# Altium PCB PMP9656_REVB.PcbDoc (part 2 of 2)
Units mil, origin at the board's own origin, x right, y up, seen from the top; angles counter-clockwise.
Board outline 5000 x 2000 mil, 4 copper layers (Top Layer, MidLayer1, MidLayer2, Bottom Layer), stack 60.2 mil thick; 89 components, 41 nets, 276 pads, 85 vias.
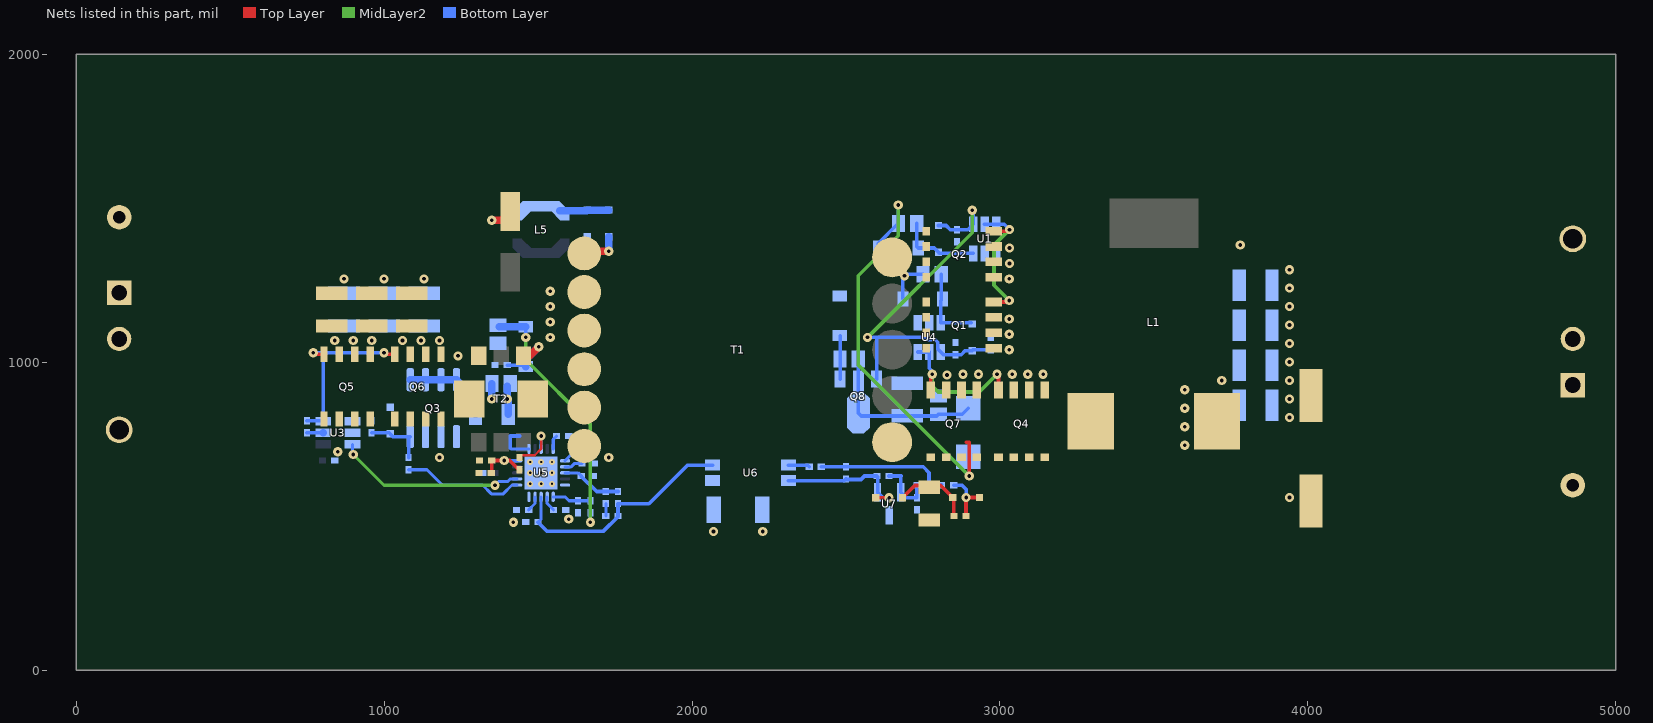
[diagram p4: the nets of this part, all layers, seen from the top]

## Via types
v1: diameter 30, hole 12, Top Layer to Bottom Layer, 76 vias
v2: diameter 19.68, hole 7.87, Top Layer to Bottom Layer, 9 vias

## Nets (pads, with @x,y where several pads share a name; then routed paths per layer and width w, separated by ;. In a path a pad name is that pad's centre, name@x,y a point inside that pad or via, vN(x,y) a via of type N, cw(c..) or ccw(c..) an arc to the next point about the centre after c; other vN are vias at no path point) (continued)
CS: D4.1 R5.2 R10.1 | length 836.7
  MidLayer2 w12: v1(1460,1080) 1460,1007.5 1670,797.5 v1(1670,480)
  Bottom Layer w12: v1(1460,1080) D4.1@1460,1114.47 ; v1(1670,480) R10.1@1670,510.32
  Bottom Layer w25: R5.2@1375.06,1114.47 D4.1@1460,1114.47
GND: C1.2 C2.1 C9.2 C10.2 C11.2 C12.2 C13.2 C16.2 C18.2 C20.2 C33.2 D12.2 J2.2 Q1.1 Q1.2 Q1.3 Q2.1 Q2.2 Q2.3 Q4.1 Q4.2 Q4.3 Q7.1 Q7.2 Q7.3 R2.1 R29.1 TP4.1 U1.4 U1.5 U4.4 U4.5 U7.3
  other v1: 2230,450 3940,560 3720,940 2827.65,958 2880,960 2930,960 3040,960 3090,960 3140,960 3030,1040 3030,1090 3030,1140 3030,1270 3030.71,1320 3030.71,1370 3780,1380
N_DRV: U3.6 U5.12 | length 611.9
  MidLayer2 w10: v1(900,700) 1000,600 v1(1360,600)
  Bottom Layer w10: v1@897.24,702.76 U3.6@897.24,732.6 ; v1(1360,600) 1372,612 1401.6,612 1409.91,620.32 U5.12@1432.24,620.32
NetC14_1: C14.1 Q3.5 Q3.6 Q3.7 Q3.8 | length 288.1
  Bottom Layer w25: Q3.5@1085,942.52 Q3.6@1135,942.52 Q3.7@1185,942.52 Q3.8@1235,942.52 1296.85,880.67 C14.1@1296.85,830
NetC14_2: C14.2 R3.2 T1.4 T1.5 T2.8 | length 91.8
  Bottom Layer w25: R3.2@1400,920.47 v1(1400,880) 1403.15,876.85 C14.2@1403.15,830
NetC15_2: C15.2 D5.2 Q3.4 R4.2 | length 195.1
  Bottom Layer w12: R4.2@960,770.31 D5.2@1016.38,770.31 ; D5.2@1020,766.69 1029.21,757.48 Q3.4@1085,757.48 1080,752.48 C15.2@1080,689.69
NetC16_1: C16.1 D3.1 Q8.2 Q8.4 R2.2 R7.2 | length 546.4
  Bottom Layer w12: R7.2@2540,1009.53 Q8.2@2540,936.93 Q8.4@2540,834.57 2549.54,825.03 R2.2@2698.13,825.03 2794.56,825.03 C16.1@2800,830.47 2877.3,830.47 D3.1@2897.09,850.26
NetC22_2: C22.2 R10.2 U5.6 | length 125.8
  Bottom Layer w10: U5.6@1549.37,562.24 1587.76,562.24 1600.31,549.69 C22.2@1630,549.69 R10.2@1670,549.69
NetC23_2: C23.2 U5.9 | length 50.8
  Bottom Layer w10: C23.2@1469.69,520 1490.32,540.63 U5.9@1490.32,562.24
NetC25_2: C25.2 R12.1 R17.2 U5.15 | length 185
  Top Layer w12: C25.2@1347.87,640 1349.69,641.81 R17.2@1349.69,680 v1(1390,680) 1408.23,680 1437.92,650.32 R12.1@1440,650.32
  Bottom Layer w10: v1@1390.63,679.37 U5.15@1432.24,679.37
NetC27_1: C27.1 D10.2 R23.1 U6.2 U7.1 | length 432.4
  Top Layer w12: D10.2@2596.69,559.68 v1(2640,559.68)
  Bottom Layer w12: U6.2@2313.03,615 2494.68,615 R23.1@2500,620.32 ; R23.1@2500,618.86 2548.86,618.86 2560,630 C27.1@2600.32,630 ; C27.1@2602.6,627.72 U7.1@2602.6,577.4 2620.32,559.68 v1(2640,559.68)
NetC27_2: C27.2 R24.1 R29.2 U7.2 | length 193.9
  Bottom Layer w12: C27.2@2639.69,630 2679.68,630 2677.4,627.72 U7.2@2677.4,577.4 2695.12,559.69 R29.2@2730,559.69 2730,599.68 R24.1@2730.32,600
NetC29_1: C29.1 R25.1 R26.1 U5.3 | length 198.4
  Bottom Layer w10: U5.3@1587.76,640 1630.32,640 C29.1@1640.32,630
  Bottom Layer w12: C29.1@1640.32,630 1640.32,627.92 1662.08,606.16 1664.16,606.16 1690.63,579.68 R25.1@1720,579.68 R26.1@1760,579.68
NetC31_1: C31.1 C32.1 R26.2 U5.8 U6.4 | length 779.1
  Bottom Layer w10: C32.1@1499.68,480 1510,490.32 U5.8@1510,562.24
  Bottom Layer w12: C32.1@1499.68,480 1528.68,451 1712.77,451 1759.68,497.92 C31.1@1759.68,500 1759.68,540 1860,540 1985,665 U6.4@2066.97,665
NetC31_2: C31.2 R25.2 | length 40
  Bottom Layer w10: C31.2@1720.31,500 R25.2@1720.31,540
NetC33_1: C33.1 D10.1 D11.2 R28.1 | length 257.6
  Top Layer w12: D10.1@2683.31,559.68 2722.99,599.37 2770,599.37 2807.32,599.37 D11.2@2846.69,560 2850.32,556.38 R28.1@2850.32,500
NetD1_2: D1.2 D2.2 R1.2 U1.6 | length 267.3
  Bottom Layer w12: R1.2@2729.53,1450 2729.53,1374.94 D2.2@2734.47,1370 2786.69,1370 D1.2@2800,1356.69 2803.94,1352.76 U1.6@2912.6,1352.76
NetD4_2: D4.2 R6.2 T2.1 | length 206.2
  Top Layer w25: T2.1@1453,1020 1472.5,1020 v1(1502.5,1050)
  Bottom Layer w12: R6.2@1399.69,990 1455.53,990 D4.2@1460,985.53
  Bottom Layer w25: D4.2@1460,985.53 1460,1007.5 v1(1502.5,1050)
NetD6_1: D6.1 D7.1 L5.2 | length 159.9
  Bottom Layer w25: L5.2@1571.02,1491.02 1657.72,1491.02 D7.1@1660,1493.31 D6.1@1730,1493.31
NetD6_2: D6.2 T1.1 | length 129.8
  Top Layer w25: T1.1@1650,1352.6 1657.4,1360 v1(1730,1360)
  Bottom Layer w25: v1(1730,1360) D6.2@1730,1406.69
NetD8_2: D8.2 D9.2 R9.2 U4.6 | length 257
  Bottom Layer w12: R9.2@2808.85,1285 2808.85,1200.22 2807.4,1198.77 U4.6@2807.4,1127.24 D8.2@2906.06,1127.24
NetD12_1: D12.1 Q8.1 R7.1 | length 139.8
  Bottom Layer w12: Q8.1@2480.94,944.8 D12.1@2480.94,1084.59
NetQ1_4: Q1.4 Q2.4 U1.2 U1.3 | length 451.1
  Top Layer w12: Q1.4@2979.3,1195 v1@3025,1195 ; Q2.4@2979.3,1425 v1@3025.71,1425
  MidLayer2 w12: v1(3030,1200) 2980.69,1249.31 2980.69,1379.98 v1(3030.71,1430)
  Bottom Layer w12: U1.2@2950,1447.24 U1.3@2987.4,1447.24 3013.46,1447.24 v1(3030.71,1430)
NetQ4_4: Q4.4 Q7.4 U4.2 U4.3 | length 485.5
  Top Layer w12: Q7.4@2775,909.3 v1@2775,955 ; Q4.4@2995,909.3 v1@2995,955
  MidLayer2 w12: v1(2780,960) 2780,922.14 2799.61,902.52 2932.52,902.52 v1(2990,960)
  Bottom Layer w12: U4.3@2732.6,1032.76 U4.2@2770,1032.76 2770,980 2780,970 v1(2780,960)
NetQ5_4: Q5.4 Q6.4 R100.2 U3.3 | length 567.7
  Top Layer w12: v1@774.88,1025.12 Q5.4@805,1025.12 ; v1@1004.88,1025.12 Q6.4@1035,1025.12
  Bottom Layer w12: R100.2@750,809.69 800.47,809.69 U3.3@802.76,807.4 802.76,1027.24 800,1030 ; v1(770,1030) 800,1030 ; v1(1000,1030) 800,1030
NetQ5_5: Q5.5 Q5.6 Q5.7 Q5.8 Q6.5 Q6.6 Q6.7 Q6.8 R3.1 T2.7 | length 49.5
  Bottom Layer w25: v1(1350,880) R3.1@1350,929.53
NetR13_2: R13.2 R20.2 R23.2 R24.2 | length 439.7
  Bottom Layer w12: R20.2@2419.69,660 R23.2@2499.69,660 ; R23.2@2500,659.69 2750.63,659.69 2769.69,640.63 R24.2@2769.69,600 R13.2@2810.31,600 R13.2@2810.31,600.82
NetR14_2: R14.2 U5.20 | length 46.8
  Bottom Layer w10: U5.20@1549.37,717.76 1549.37,749.06 R14.2@1560.31,760
NetR15_2: R15.2 U5.7 | length 50.8
  Bottom Layer w10: U5.7@1529.68,562.24 1529.68,540.63 R15.2@1550.31,520
NetR19_2: R19.2 U5.1 | length 65.2
  Bottom Layer w10: U5.1@1587.76,679.37 1618.39,710 R19.2@1640.31,710
NetR20_1: R20.1 U6.1 | length 69.4
  Bottom Layer w12: U6.1@2313.03,665 2375.32,665 R20.1@2380.32,660
NetR22_2: R22.2 U5.2 | length 60.1
  Bottom Layer w10: U5.2@1587.76,659.68 1607.63,659.68 1619,671.05 R22.2@1643.16,671.05
NetR100_1: R100.1 U3.2 | length 52.9
  Bottom Layer w12: R100.1@750,770.32 U3.2@802.44,770.32
  Bottom Layer w25: U3.2@802.44,770.32 U3.2@802.76,770
P_DRV: C15.1 U5.11 | length 396.5
  Bottom Layer w10: C15.1@1080,650.32 1139.68,650.32 1189.37,600.63 1319.77,600.63 1348.4,572 1387.05,572 1415.68,600.63 U5.11@1432.24,600.63
PGND: C2.2 C3.2 C4.2 C5.2 C6.2 C7.2 C8.2 C19.1 C21.2 C22.1 C23.1 C25.1 C28.2 C29.2 C32.2 D5.1 D7.2 J1.2 Q3.1 Q3.2 Q3.3 Q5.1 Q5.2 Q5.3 Q6.1 Q6.2 Q6.3 R4.1 R5.1 R6.1 R14.1 R15.1 R17.1 R19.1 R22.1 T1.6 T2.3 TP3.1 U3.4 U3.5 U5.5 U5.10 U5.16 U5.21 U6.3 | length 201.1
  Top Layer w25: v1(1350,1460) 1381.57,1460 C21.2@1410,1488.43
  Bottom Layer w10: 1411.93,717.76 U5.16@1470.63,717.76
  Bottom Layer w12: 1409.69,720 1409.69,760 1440.32,760
  other v1: 2070,450 1420,480 1600,490 1180,690 1730,690 850,708.98 1240,1020 840,1070 900,1070 960,1070 1060,1070 1120,1070 1180,1070
  other v2: 1474.57,604.57 1510,604.57 1545.43,604.57 1474.57,640 1510,640 1545.43,640 1474.57,675.43 1510,675.43 1545.43,675.43
VDRV: C1.1 C18.1 C20.1 D1.1 D8.1 Q8.3 U1.1 U4.1 | length 1300.2
  MidLayer2 w12: v1(2570,1080) 2910,1420 v1(2910,1492.52)
  Bottom Layer w12: v1(2570,1080) 2600,1080 ; Q8.3@2599.06,944.8 2600.32,946.06 2600.32,1079.68 2600,1080 ; D1.1@2800,1443.31 2824.67,1443.31 2838.3,1429.68 C1.1@2860,1429.68 2895.04,1429.68 U1.1@2912.6,1447.24 v1@2912.6,1489.92 ; C18.1@2970,1040.32 2913.62,1040.32 D8.1@2910,1036.69 2886.69,1036.69 2873.86,1023.86 C20.1@2855.3,1023.86 2816.3,1023.86 U4.1@2807.4,1032.76 2797.78,1042.38 2797.78,1064.15 2789.58,1072.35 2767.81,1072.35 2760.16,1080 2600,1080
VIN: C3.1 C4.1 C5.1 C6.1 C7.1 C8.1 J1.1 R12.2 T1.2 T1.3 TP1.1 U5.18 | length 166.1
  Top Layer w8: R12.2@1440,689.69 1447.59,697.28 1489.52,697.28 1510,717.76 v1(1510,760)
  Bottom Layer w10: U5.18@1510,717.76 v1(1510,760)
  other v1: 1540,1080 1540,1130 1540,1180 1540,1230 870,1270 1000,1270 1130,1270
VOUT: C9.1 C10.1 C11.1 C12.1 C13.1 D11.1 J2.1 L1.2 R13.1 R28.2 TP2.1 | length 175.4
  Top Layer w12: R28.2@2889.69,500 v1@2889.69,559.69 ; v1(2890,560) D11.1@2933.31,560
  Bottom Layer w12: R13.1@2849.68,600 2876.56,600 2890,586.57 v1(2890,560)
  other v1: 3600,730 3600,790 3940,820 3600,850 3940,880 3600,910 3940,940 3940,1000 3940,1060 3940,1120 3940,1180 3940,1240 3940,1300
VSEC1: D9.1 Q1.5 Q1.6 Q1.7 Q1.8 Q2.5 Q2.6 Q2.7 Q2.8 R9.1 T1.11 | length 132
  Bottom Layer w12: D9.1@2684.69,1205 2684.69,1274.69 v1(2690,1280) ; v1@2695,1285 R9.1@2749.79,1285
VSEC2: D2.1 D3.2 L1.1 Q4.5 Q4.6 Q4.7 Q4.8 Q7.5 Q7.6 Q7.7 Q7.8 R1.1 T1.7 | length 1429.5
  Top Layer w12: 2890,740 2900,740 v1(2900,630)
  MidLayer2 w12: v1(2670,1510) 2670,1410 2540,1280 2540,990 v1(2900,630)
  Bottom Layer w12: D2.1@2605.53,1370 2605.53,1386 2670,1450.47 v1(2670,1510) ; v1(2900,630) D3.2@2900,689.87
pads on no net: L1.3 T1.8 T1.9 T1.10 T2.2 T2.4 T2.5 T2.6 U5.4 U5.17 U5.19

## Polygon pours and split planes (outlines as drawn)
GND on MidLayer1 "GND_L02_P067" (solid, remove dead copper, pour order 67): 2200,25.24 2200,1974.76 4974.76,1974.76 4974.76,25.24
PGND on MidLayer1 "MidLayer1-PGND" (solid, remove dead copper, pour order 59): 10,1990 10,0 2100,0 2100,1990
VIN on MidLayer2 "MidLayer2-VIN" (solid, remove dead copper, pour order 61): 10,1990 10,10 2100,10 2100,1990
VOUT on MidLayer2 "MidLayer2-VOUT" (solid, remove dead copper, pour order 60): 2200,1990 2200,10 4990,10 4990,1990
PGND on Bottom Layer "Bottom Layer-PGND" (solid, remove dead copper, pour order 64): 20,1990 20,10 2100,10 2100,1990
VIN on Bottom Layer "Bottom Layer-VIN" (solid, remove dead copper, pour order 63): 810,1324.99 810,1180 1191.26,1180 1191.26,1324.99
GND on Bottom Layer "Bottom Layer-GND" (solid, remove dead copper, pour order 65): 2200,2000 2200,20 4980,20 4980,2000
VOUT on Bottom Layer "Bottom Layer-VOUT" (solid, remove dead copper, pour order 62): 3840,1330 3840,790 4000,790 4000,1330
VSEC2 on Top Layer "Top Layer-VSEC2" (solid, remove dead copper, pour order 49): 3200,920 3200,720 3380,720 3380,920
VSEC2 on Top Layer "Top Layer-VSEC2" (solid, remove dead copper, pour order 50): 2580,920 2580,730 2731.26,730 2731.26,920
VSEC2 on Top Layer "Top Layer-VSEC2" (solid, remove dead copper, pour order 51): 2580,860 2580,650 3380,650 3380,860
VSEC1 on Top Layer "Top Layer-VSEC1" (solid, remove dead copper, pour order 53): 2580,1450 2580,1020 2920,1020 2920,1450
PGND on Top Layer "Top Layer-PGND" (solid, remove dead copper, pour order 58): 10,1980 10,10 2100,10 2100,1980
VIN on Top Layer "Top Layer-VIN" (solid, remove dead copper, pour order 56): 1341.46,1200 1341.46,1000 1830,1000 1830,1200
VIN on Top Layer "Top Layer-VIN" (solid, remove dead copper, pour order 55): 10,1990 10,1180 1830,1180 1830,1990
NetQ5_5 on Top Layer "Top Layer-Drain2" (solid, remove dead copper, pour order 54): 778.74,980 778.74,780 1370,780 1370,980
NetC14_2 on Top Layer "Top Layer-Drain1" (solid, remove dead copper, pour order 48): 1380,990 1380,760 1717.32,760 1717.32,990
VOUT on Top Layer "Top Layer-VOUT" (solid, remove dead copper, pour order 52): 3570,1330 3570,650 4974.76,650 4974.76,1330
GND on Top Layer "Top Layer-GND" (solid, remove dead copper, pour order 57): 2200,1990 2200,-2.5 4990,-2.5 4990,1990

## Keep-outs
Keep-Out Layer:
  lines w5: -2.5,0 ccw(c0,0) 0,-2.5 ; -2.5,0 ccw(c0,0) 0,-2.5 ; -2.5,0 -2.5,2000 ; -2.5,2000 cw(c0,2000) 0,2002.5 ; -2.5,2000 cw(c0,2000) 0,2002.5 ; 0,-2.5 5000,-2.5 ; 0,2002.5 5000,2002.5 ; 5000,-2.5 ccw(c5000,0) 5002.5,0 ; 5000,-2.5 ccw(c5000,0) 5002.5,0 ; 5000,2002.5 cw(c5000,2000) 5002.5,2000 ; 5000,2002.5 cw(c5000,2000) 5002.5,2000 ; 5002.5,0 5002.5,2000
  text ".Layer_Name" at 577,-858.49 h60

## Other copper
Top Layer:
  text ".Layer_Name" at 577,-858.49 h60
Bottom Layer:
  text ".Layer_Name" at 577,-858.49 h60

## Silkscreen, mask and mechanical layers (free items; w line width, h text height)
Top Overlay:
  rectangle: 3920,20 4950,140
  text "PMP9656 Rev B PCB" at 3940,160 h60
  text ".Layer_Name" at 577,-858.49 h60
Bottom Overlay:
  text ".Layer_Name" at 577,-858.49 h60
Top Paste:
  text ".Layer_Name" at 577,-858.49 h60
Bottom Paste:
  text ".Layer_Name" at 577,-858.49 h60
Top Solder:
  text ".Layer_Name" at 577,-858.49 h60
  text ".Layer_Name" at 577,-858.49 h60
Bottom Solder:
  text ".Layer_Name" at 577,-858.49 h60
Drill Guide:
  text ".Layer_Name" at 577,-858.49 h60
M1 Board Outline:
  the board outline again, w10
  text ".Layer_Name" at 577,-858.49 h60
M2 Board Dimensions:
  rectangle: 124.5,-410.5 499.5,-285.5
  rectangle: -0.5,-285.5 124.5,-160.5
  lines w7: -0.5,-285.5 999.5,-285.5 ; 124.5,-410.5 124.5,-160.5 ; 249.5,-410.5 249.5,-160.5 ; 499.5,-410.5 499.5,-160.5 ; 749.5,-410.5 749.5,-160.5 ; -0.5,-410.5 -0.5,-160.5 999.5,-160.5 999.5,-410.5 -0.5,-410.5
  lines w10: -0.5,-475.5 -0.5,-455.5 ; 59.5,-485.5 -0.5,-465.5 ; 59.5,-445.5 -0.5,-465.5 ; 223.58,-465.5 -0.5,-465.5 ; 775.42,-465.5 999.5,-465.5 ; 939.5,-485.5 999.5,-465.5 ; 939.5,-445.5 999.5,-465.5 ; 999.5,-475.5 999.5,-455.5
  text "1000 (mil)" at 233.58,-501.49 h60
  text ".Layer_Name" at 577,-858.49 h60
M3 3D STEP Top:
  text ".Layer_Name" at 577,-858.49 h60
M4 3D STEP Bottom:
  text ".Layer_Name" at 577,-858.49 h60
M5 Assembly Top:
  lines w10: -292,-930.17 6308,-930.17 ; -292,-726.83 6310,-726.83 ; -292,-523.5 -292,-1133.5 3713,-1133.5 6310,-1133.5 6310,-523.5 -291.5,-523.5 -291.5,-1133.5 1284,-1133.5 ; 2173,-1133.5 2173,-523.5 ; 3440,-726.83 3440,-523.5 ; 4280,-726.83 4280,-523.5 ; 4902,-1140 4902,-937.17
  text "COMPONENTS MARKED 'DNP' SHOULD NOT BE POPULATED." at 1153.5,-318.5 h60
  text "ASSEMBLY VARIANT:" at 1153,-434 h60
  text ".VariantName" at 2189,-434 h60
  text "PCB VIEWED FROM TOP SIDE" at -228.5,-655.67 h60
  text "BOARD #:" at 2248,-655.67 h60
  text ".PRJ_Number" at 2793.5,-655.67 h60
  text "REV:" at 3638,-655.67 h60
  text ".PCB_Rev" at 3929.5,-655.67 h60
  text "SVN REV:" at 4476,-655.67 h60
  text ".VersionControl_RevNumber" at 4982,-655.67 h60
  text "IGNORE ->" at -228.5,-858.49 h60
  text "PLOT NAME =" at -228.5,-1064.34 h60
  text ".plot_File_Name" at 577,-1064.34 h60
  text "GENERATED    :" at 2250,-1064.34 h60
  text ".Print_Date" at 3119.5,-1064.34 h60
  text ".Print_Time" at 3848.5,-1064.34 h60
  text "TEXAS INSTRUMENTS" at 5113,-1064.34 h60
M6 Assembly Bottom:
  lines w10: -292.5,-727.33 6309.5,-727.33 ; -290.5,-930.67 6309.5,-930.67 ; 1115.5,-1140.5 1115.5,-937.67 ; 1737.5,-727.33 1737.5,-524 ; 2577.5,-727.33 2577.5,-524 ; 3844.5,-1134 3844.5,-524 ; 4733.5,-1134 6309,-1134 6309,-524 -292.5,-524 -292.5,-1134 2304.5,-1134 6309.5,-1134 6309.5,-524
  text "COMPONENTS MARKED 'DNP' SHOULD NOT BE POPULATED." at 6102,-318 h60
  text ".VariantName" at 5058,-434 h60
  text "ASSEMBLY VARIANT:" at 6097,-434 h60
  text ".VersionControl_RevNumber" at 1035.5,-656.17 h60
  text "SVN REV:" at 1541.5,-656.17 h60
  text ".PCB_Rev" at 2088,-656.17 h60
  text "REV:" at 2379.5,-656.17 h60
  text ".PRJ_Number" at 3224,-656.17 h60
  text "BOARD #:" at 3769.5,-656.17 h60
  text "PCB VIEWED FROM BOTTOM SIDE" at 6246,-656.17 h60
  text "IGNORE ->" at 2547.85,-858.49 h60
  text "TEXAS INSTRUMENTS" at 904.5,-1064.84 h60
  text ".Print_Time" at 2169,-1064.84 h60
  text ".Print_Date" at 2898,-1064.84 h60
  text "GENERATED    :" at 3767.5,-1064.84 h60
  text ".plot_File_Name" at 5440.5,-1064.84 h60
  text "PLOT NAME =" at 6246,-1064.84 h60
M9 Title Sheet:
  drawing of 57 lines, arcs and shapes, not listed
  text "1" at 739.84,8036.5 h70
  text "2" at 3235.5,8036.5 h70
  text "3" at 5724.84,8036.5 h70
  text "4" at 8231.51,8036.5 h70
  text "5" at 10730.5,8036.5 h70
  text "6" at 13235.5,8036.5 h70
  text "A" at -416.5,6893.5 h70
  text "A" at 14383.5,6893.5 h70
  text "B" at -416.5,4513.5 h70
  text "B" at 14383.5,4513.5 h70
  text "C" at -416.5,2138.5 h70
  text "C" at 14383.5,2138.5 h70
  text "PROJECT TITLE:" at 11343.5,277.5 h45
  text ".PRJ_Title" at 11393.5,144.17 h70
  text "DESIGNED FOR:" at 11343.5,-23.5 h45
  text ".PRJ_Customer" at 11393.5,-163.5 h70
  text "D" at -416.5,-231.5 h70
  text "D" at 14383.5,-231.5 h70
  text "FILE NAME:" at 11343.5,-323.5 h45
  text ".PCB_File_Name_No_Path" at 11393.5,-443.5 h70
  text "Texas Instruments (TI) and/or its licensors do not warrant the accuracy or completeness of this specification" at 6374,-605.34 h45
  text "ENGINEER:" at 11343.5,-613.5 h45
  text "LAYOUT BY:" at 12848.5,-613.5 h45
  text "or any information contained therein. TI and/or its licensors do not warrant that this design will meet" at 6329.01,-718 h45
  text ".PRJ_Engineer" at 11393.5,-768.49 h70
  text ".PCB_Layout" at 12899,-768.49 h70
  text "the specifications, will be suitable for your application or fit for any particular purpose, or will operate in" at 6329.01,-830.67 h45
  text ".Layer_Name" at 577,-858.49 h60
  text "ALTIUM DESIGNER VERSION:" at 12848.5,-923.5 h45
  text "an implementation. TI and/or its licensors do not warrant that the design is production worthy. You should" at 6329.01,-943.33 h45
  text "completely validate and test your design implementation to confirm the system functionality for your application." at 6374,-1056 h45
  text ".print_Scale" at 11393.5,-1056.83 h70
  text ".Application_BuildNumber" at 12899,-1056.83 h70
  text "1" at 739.84,-1263.5 h70
  text "2" at 3235.5,-1263.5 h70
  text "3" at 5724.84,-1263.5 h70
  text "4" at 8231.51,-1263.5 h70
  text "5" at 10730.5,-1263.5 h70
  text "6" at 13235.5,-1263.5 h70
M10 Fab Notes:
  drawing of 212 lines, arcs and shapes, not listed
  text "DESIGN INFORMATION" at 12381.02,6810 h60
  text "(REFER ALSO ARRAY/PANEL PROFILING INFORMATION)" at 12019.46,6648.29 h60
  text "BOARD SIZE" at 11333.46,6644 h60
  text "X" at 12301.46,6516.18 h60
  text "Number of Layers :" at 11736.46,6319 h60
  text "4" at 12831.27,6309 h60
  text "MIN. TRACK WIDTH:" at 11736.46,6180 h60
  text "8" at 12832.7,6180 h60
  text "MIL" at 12987.46,6180 h60
  text "MIN. CLEARANCE:" at 11736.46,6048 h60
  text "8" at 12832.7,6048 h60
  text "MIL" at 12987.46,6048 h60
  text "MIN. VIA PAD SIZE:" at 11736.46,5916 h60
  text "24" at 12802.71,5916 h60
  text "MIL" at 12987.46,5916 h60
  text "0.05mm (2MIL)" at 12431.46,5774.29 h60
  text "MINIMUM ANNULAR RING" at 11407.23,5770 h60
  text "EXTERNAL" at 13139.46,5770 h60
  text "PER" at 11607.23,5652 h60
  text "IPC-D-275 CLASS 2 LEVEL C" at 11827.23,5652 h60
  text "MIL, HOLES" at 13315.46,5539.71 h60
  text "+/-" at 12923,5539 h60
  text "+/-" at 13777,5539 h60
  text "REGISTRATION TOLERANCES:" at 11407.23,5534 h60
  text "METAL" at 12607,5534 h60
  text "5" at 13183.2,5534 h60
  text "3" at 14016.2,5534 h60
  text "MIL" at 14132.46,5534 h60
  text "MATERIAL:" at 11332.46,5324.54 h60
  text "FR-4 High Tg" at 12318.9,5184.21 h60
  text "FR-408" at 11753.46,5175.64 h60
  text "X" at 12165.46,5175.64 h60
  text "OTHER" at 13241.46,5175.64 h60
  text "62 MIL (1.6mm) +/-10%" at 12073.56,5012.92 h60
  text "THICKNESS:" at 11407.23,5008.64 h60
  text "X" at 11945.4,5008.64 h60
  text "OTHER" at 13358.46,5008.64 h60
  text "TOLERANCE:" at 11407.23,4850.64 h60
  text "X" at 12246.53,4850.64 h60
  text "ANSI IPC-6012 TYPE 3 CLASS 2" at 12433.48,4850.64 h60
  text "OTHER +/-" at 12433.46,4694.64 h60
  text "BOW & TWIST:" at 11407.23,4537.64 h60
  text "X" at 12246.53,4537.64 h60
  text "ANSI IPC-6012 TYPE 3 CLASS 2" at 12433.48,4537.64 h60
  text "OTHER +/-" at 12433.46,4379.13 h60
  text "COPPER THICKNESS (FINISHED):" at 11332.46,4243.64 h60
  text "1.4MIL (1oz)" at 12212.46,4090.92 h60
  text "2MIL (1.4oz)" at 12979.46,4090.92 h60
  text "2.8MIL (2oz)" at 13706.46,4090.92 h60
  text "OUTER:" at 11689.46,4086.64 h60
  text "X" at 12084,4086 h60
  text "1.4MIL (1oz)" at 12212.46,3933.92 h60
  text "2.8MIL (2oz)" at 12979.46,3933.92 h60
  text "N/A" at 13706,3934.29 h60
  text "INNER SIGNAL:" at 11400.38,3929.64 h60
  text "X" at 12085.42,3929.64 h60
  text "DRILLING:" at 11332.46,3790.64 h60
  text "REFERENCE:" at 11407.23,3673.64 h60
  text "X" at 12055.46,3673.64 h60
  text "AS SHOWN" at 12242.46,3673.64 h60
  text "X" at 12956.46,3673.64 h60
  text "NC_DRILL FILES" at 13093.46,3673.64 h60
  text "PTH MIN COPPER THICKNESS:" at 11407.23,3515.64 h60
  text "X" at 12757.46,3515.64 h60
  text "1MIL" at 12894.46,3515.64 h60
  text "OTHER" at 13391.46,3515.64 h60
  text "BOARD FINISH:" at 11332.46,3356.64 h60
  text "SILKSCREEN:" at 11487.68,3238.64 h60
  text "X" at 12436.46,3238.64 h60
  text "TOP" at 12562.46,3238.64 h60
  text "X" at 12946.46,3238.64 h60
  text "BOTTOM" at 13073.46,3238.64 h60
  text "SILKSCREEN COLOR:" at 11487.68,3071.64 h60
  text "X" at 12435.42,3071.64 h60
  text "WHITE" at 12562.46,3071.64 h60
  text "OTHER" at 13073.46,3071.64 h60
  text "SOLDER RESIST COLOR:" at 11487.68,2901.64 h60
  text "X" at 12055.42,2742.44 h60
  text "GREEN" at 12182.46,2742.44 h60
  text "BLUE" at 12773.46,2742.44 h60
  text "OTHER" at 13311.46,2742.44 h60
  text "IMMERSION GOLD (ENIG)" at 12393.46,2553.92 h60
  text "ENEPIG" at 13731,2550.64 h60
  text "SURFACE FINISH:" at 11332.46,2549.64 h60
  text "IMM. TIN/SILVER OR EQUIV" at 11662,2392.64 h60
  text "OTHER" at 13093.46,2392.64 h60
  text "X" at 11490,2390 h60
  text "ARRAY/PANEL:" at 11332.46,2213.64 h60
  text "CUT AND TRIM PER MECH LAYER 1" at 12393.46,2209.35 h60
  text "N.C. ROUTE" at 12393.46,2057.64 h60
  text "X" at 13072.46,2057.64 h60
  text "V. SCORE" at 13259.46,2057.64 h60
  text "CERTIFICATION:" at 11332.46,1920.64 h60
  text "MATERIALS AND WORKMANSHIP FOR ALL PCBS" at 12057.46,1920.64 h60
  text "TO MEET OR EXCEED THE REQUIREMENTS OF:" at 12057.46,1822.64 h60
  text "X" at 11683.96,1686.13 h60
  text "ANSI IPC-A-600F CLASS ->" at 11822.96,1686.13 h60
  text "X" at 13462.02,1686.13 h60
  text "2" at 13580.96,1686.14 h60
  text "1" at 13265.96,1684.64 h60
  text "3" at 13934.96,1684.64 h60
  text "X" at 11686.02,1526.64 h60
  text "UL 94V-0" at 11822.96,1526.64 h60
  text "X" at 12498.02,1526.64 h60
  text "RoHS" at 12634.96,1526.64 h60
  text "OTHER" at 13279.36,1526.64 h60
  text "PER ORDER" at 13676.42,1526.64 h60
  text "ADDITIONAL REQUIREMENTS:" at 11332.46,1385.64 h60
  text "MICROSECTION:" at 11407.23,1270.64 h60
  text "YES" at 12312.96,1270.64 h60
  text "REQUIRED" at 13174.46,1114.49 h60
  text "BARE BOARD ELEC. TEST:" at 11407.23,1111.64 h60
  text "NONE" at 12712.96,1111.64 h60
  text "X" at 13047.46,1111.64 h60
  text "PER ORDER" at 13766.46,1111.64 h60
  text "MANUFACTURER'S UL:" at 11407.23,954.64 h60
  text "RAIL" at 12572.96,950.35 h60
  text "METAL" at 13064.77,950.35 h60
  text "X" at 13440,950 h60
  text "SILK" at 13576.46,950.35 h60
  text ".Layer_Name" at 577,-858.49 h60
M11 Gerber Information:
  lines w10: -292,-930.17 6308,-930.17 ; -292,-726.83 6310,-726.83 ; -292,-523.5 -292,-1133.5 3713,-1133.5 6310,-1133.5 6310,-523.5 -291.5,-523.5 -291.5,-1133.5 1284,-1133.5 ; 2173,-1133.5 2173,-523.5 ; 3440,-726.83 3440,-523.5 ; 4280,-726.83 4280,-523.5 ; 4902,-1140 4902,-937.17
  text "ALL ARTWORK VIEWED FROM TOP SIDE" at -228.5,-655.67 h60
  text "BOARD #:" at 2248,-655.67 h60
  text ".PRJ_Number" at 2793.5,-655.67 h60
  text "REV:" at 3638,-655.67 h60
  text ".PCB_Rev" at 3929.5,-655.67 h60
  text "SVN REV:" at 4476,-655.67 h60
  text ".VersionControl_RevNumber" at 4982,-655.67 h60
  text "LAYER NAME =" at -228.5,-858.49 h60
  text "PLOT NAME =" at -228.5,-1064.34 h60
  text ".plot_File_Name" at 577,-1064.34 h60
  text "GENERATED    :" at 2250,-1064.34 h60
  text ".Print_Date" at 3119.5,-1064.34 h60
  text ".Print_Time" at 3848.5,-1064.34 h60
  text "TEXAS INSTRUMENTS" at 5113,-1064.34 h60
M12 Stackup:
  lines w6: 11350,7698 14230,7698 ; 11350,7814.7 14230,7814.7 ; 11290,6968 ccw(c11328,6968) 11328,6930 14252,6930 ccw(c14252,6968) 14290,6968 14290,7912 ccw(c14252,7912) 14252,7950 11328,7950 ccw(c11328,7912) 11290,7912 11290,6968
  text "Layer Stack Up Detail for: PMP9656_REVA.PcbDoc" at 11350,7843.75 h52
  text "Layer" at 11350,7771.2 h27
  text "Gerber" at 12359.79,7771.2 h27
  text "Copper" at 13002.9,7771.2 h27
  text "Dielectric" at 13690.1,7771.2 h27
  text "Name" at 11350,7717.2 h27
  text "Document" at 12359.79,7717.2 h27
  text "Thickness" at 13002.9,7717.2 h27
  text "Material" at 13690.1,7717.2 h27
  text "Top Solder Mask" at 11350,7641.88 h38
  text "(.GTS)" at 12359.79,7641.88 h38
  text "Solder Resist" at 13690.1,7641.88 h38
  text "Top Layer" at 11350,7535.62 h38
  text "(.GTL)" at 12359.79,7535.62 h38
  text "1.4mil" at 13002.9,7535.62 h38
  text "FR-4" at 13690.1,7482.5 h38
  text "MidLayer1" at 11350,7429.38 h38
  text "(.G1)" at 12359.79,7429.38 h38
  text "1.4mil" at 13002.9,7429.38 h38
  text "FR-4" at 13690.1,7376.25 h38
  text "MidLayer2" at 11350,7323.12 h38
  text "(.G2)" at 12359.79,7323.12 h38
  text "1.4mil" at 13002.9,7323.12 h38
  text "FR-4" at 13690.1,7270 h38
  text "Bottom Layer" at 11350,7216.88 h38
  text "(.GBL)" at 12359.79,7216.88 h38
  text "1.4mil" at 13002.9,7216.88 h38
  text "Bottom Solder Mask" at 11350,7110.62 h38
  text "(.GBS)" at 12359.79,7110.62 h38
  text "Solder Resist" at 13690.1,7110.62 h38
  text ".Layer_Name" at 577,-858.49 h60
M13 Component Bodies Top:
  text ".Layer_Name" at 577,-858.49 h60
M14 Component Bodies Bottom:
  text ".Layer_Name" at 577,-858.49 h60
M15 Courtyards Top:
  text ".Layer_Name" at 577,-858.49 h60
M16 Courtyards Bottom:
  text ".Layer_Name" at 577,-858.49 h60
Drill Drawing:
  text ".legend" at 5272.5,195.5 h60
  text "Drill Table" at 5297.5,10.5 h60
  text ".Layer_Name" at 577,-858.49 h60

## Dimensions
0,0 to 5000,0 on M2 Board Dimensions
0,0 to 0,2000 on M2 Board Dimensions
